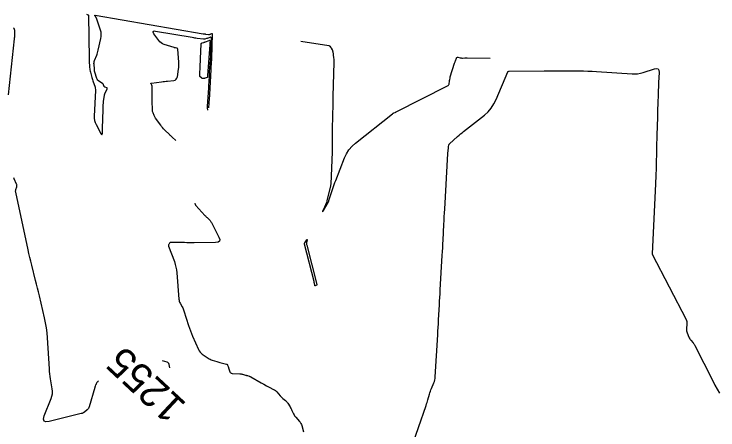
# Model space of a CAD drawing. Extents: x 658976 to 668721, y 639543 to 647196.
# Drawn here: x 660167.2 to 660311.5, y 642702 to 642787.3 of the extents above; entities that cross this region are included whole.
import ezdxf

# ---------------------------------------------------------------- set-up
doc = ezdxf.new("R2010")
doc.units = 0
for name, color, linetype in [('Ex_Contour Labels', 7, 'Continuous'), ('Ex_Major Contours', 7, 'Continuous'), ('Ex_Minor Contours', 7, 'Continuous')]:
    doc.layers.add(name, color=color, linetype=linetype)

msp = doc.modelspace()

# ---------------------------------------------------------------- linework, layer by layer
at = {"layer": 'Ex_Major Contours'}
for points in [[(660166.01, 642770.76), (660167.28, 642782.28), (660167.3, 642782.49), (660167.32, 642782.7), (660167.32, 642782.92), (660167.32, 642783.13), (660167.31, 642783.99), (660167.28, 642784.19), (660167.21, 642784.36), (660167.09, 642784.5)], [(660200.38, 642761.4), (660199.6, 642762.09), (660199.47, 642762.2), (660199.34, 642762.32), (660199.22, 642762.44), (660199.09, 642762.56), (660198.03, 642763.6), (660197.82, 642763.82), (660197.61, 642764.04), (660197.42, 642764.28), (660197.24, 642764.52), (660196.2, 642765.98), (660196.11, 642766.11), (660196.04, 642766.23), (660195.97, 642766.36), (660195.9, 642766.5), (660195.67, 642767.04), (660195.61, 642767.18), (660195.58, 642767.32), (660195.55, 642767.47), (660195.54, 642767.61), (660195.52, 642769.55), (660195.52, 642769.86), (660195.52, 642770.16), (660195.51, 642770.47), (660195.51, 642770.78), (660195.5, 642772.45), (660195.49, 642772.53), (660195.47, 642772.61), (660195.45, 642772.68), (660195.41, 642772.75), (660195.26, 642773.03), (660195.23, 642773.1), (660195.24, 642773.14), (660195.27, 642773.18), (660195.34, 642773.19), (660197.4, 642773.43), (660197.72, 642773.47), (660198.03, 642773.51), (660198.35, 642773.54), (660198.67, 642773.58), (660199.93, 642773.74), (660200.21, 642773.81), (660200.43, 642773.96), (660200.58, 642774.17), (660200.66, 642774.45), (660200.9, 642776), (660200.94, 642776.36), (660200.97, 642776.72), (660200.97, 642777.09), (660200.95, 642777.45), (660200.76, 642780.12), (660200.74, 642780.19), (660200.71, 642780.24), (660200.66, 642780.28), (660200.6, 642780.31), (660200.31, 642780.38), (660200.23, 642780.4), (660200.16, 642780.42), (660200.09, 642780.44), (660200.02, 642780.47), (660197.98, 642781.09), (660197.64, 642781.23), (660197.33, 642781.41), (660197.06, 642781.65), (660196.83, 642781.94), (660195.87, 642783.32), (660195.72, 642783.61), (660195.72, 642783.79), (660195.89, 642783.87), (660196.21, 642783.86), (660203.7, 642782.57), (660203.94, 642782.53), (660204.19, 642782.49), (660204.44, 642782.46), (660204.69, 642782.42), (660206.02, 642782.24), (660206.1, 642782.24), (660206.19, 642782.24), (660206.28, 642782.25), (660206.36, 642782.27), (660206.7, 642782.37), (660206.79, 642782.39), (660206.87, 642782.42), (660206.95, 642782.45), (660207.04, 642782.48), (660207.41, 642782.63), (660207.48, 642782.65), (660207.54, 642782.63), (660207.57, 642782.59), (660207.58, 642782.51), (660207.51, 642780.32), (660207.49, 642779.93), (660207.48, 642779.53), (660207.45, 642779.13), (660207.43, 642778.74), (660207.2, 642775.52), (660207.19, 642775.47), (660207.19, 642775.42), (660207.19, 642775.36), (660207.19, 642775.31), (660207.18, 642775.1), (660207.18, 642775.05), (660207.17, 642775), (660207.17, 642774.95), (660207.17, 642774.89), (660207.09, 642773.26), (660207.07, 642772.97), (660207.05, 642772.68), (660207.04, 642772.39), (660207.02, 642772.1), (660206.79, 642768.41), (660206.79, 642768.39), (660206.79, 642768.36), (660206.78, 642768.33), (660206.78, 642768.31), (660206.77, 642768.2), (660206.77, 642768.18), (660206.77, 642768.15), (660206.77, 642768.12), (660206.77, 642768.1), (660206.81, 642767.59)], [(660184.46, 642712.05), (660184.36, 642711.93), (660184.31, 642711.88), (660184.26, 642711.82), (660184.22, 642711.76), (660184.18, 642711.7), (660184.02, 642711.45), (660183.99, 642711.39), (660183.96, 642711.33), (660183.93, 642711.27), (660183.9, 642711.21), (660183.81, 642710.96), (660183.79, 642710.9), (660183.77, 642710.83), (660183.75, 642710.77), (660183.73, 642710.71), (660182.6, 642706.75), (660182.53, 642706.57), (660182.45, 642706.41), (660182.33, 642706.27), (660182.2, 642706.14), (660181.61, 642705.66), (660181.46, 642705.55), (660181.29, 642705.45), (660181.12, 642705.38), (660180.94, 642705.33), (660174.36, 642703.72), (660173.7, 642703.65), (660173.32, 642703.81), (660173.21, 642704.21), (660173.37, 642704.85), (660174.79, 642708.45), (660174.94, 642708.94), (660175.03, 642709.43), (660175.05, 642709.92), (660175, 642710.43), (660174.66, 642712.46), (660174.58, 642712.97), (660174.52, 642713.48), (660174.47, 642714), (660174.43, 642714.51), (660174.02, 642720.9), (660173.94, 642721.94), (660173.81, 642722.97), (660173.63, 642723.99), (660173.42, 642725.01), (660172.38, 642729.53), (660172.19, 642730.32), (660172, 642731.11), (660171.81, 642731.89), (660171.61, 642732.68), (660170.81, 642735.82), (660170.61, 642736.6), (660170.42, 642737.39), (660170.24, 642738.18), (660170.06, 642738.97), (660167.53, 642750.78), (660167.51, 642750.92), (660167.51, 642751.07), (660167.52, 642751.21), (660167.56, 642751.35), (660167.74, 642751.91), (660167.77, 642752.05), (660167.78, 642752.19), (660167.76, 642752.33), (660167.71, 642752.46), (660167.21, 642753.52), (660167.12, 642753.74)], [(660199.13, 642714.75), (660198.98, 642715.43), (660198.93, 642715.59), (660198.84, 642715.72), (660198.72, 642715.83), (660198.56, 642715.9), (660197.64, 642716.19), (660197.59, 642716.2)]]:
    msp.add_lwpolyline(points, dxfattribs=at)
at = {"layer": 'Ex_Minor Contours'}
for points in [[(660182.02, 642787.34), (660182.34, 642787.2), (660182.38, 642787.18), (660182.42, 642787.14), (660182.44, 642787.1), (660182.44, 642787.04), (660182.58, 642778.14), (660182.58, 642778.12), (660182.58, 642778.09), (660182.57, 642778.06), (660182.57, 642778.04), (660182.56, 642777.93), (660182.56, 642777.91), (660182.56, 642777.88), (660182.56, 642777.85), (660182.56, 642777.83), (660182.68, 642776.38), (660182.7, 642776.13), (660182.74, 642775.89), (660182.79, 642775.64), (660182.85, 642775.4), (660183.14, 642774.33), (660183.21, 642774.11), (660183.27, 642773.89), (660183.34, 642773.66), (660183.42, 642773.44), (660183.72, 642772.56), (660183.78, 642772.34), (660183.82, 642772.11), (660183.85, 642771.88), (660183.85, 642771.65), (660183.61, 642766.42), (660183.61, 642765.96), (660183.68, 642765.52), (660183.81, 642765.09), (660183.99, 642764.68), (660184.94, 642762.85), (660185.09, 642762.62), (660185.19, 642762.56), (660185.26, 642762.66), (660185.29, 642762.93), (660185.33, 642764.34), (660185.34, 642764.69), (660185.35, 642765.04), (660185.36, 642765.39), (660185.37, 642765.75), (660185.43, 642767.74), (660185.44, 642767.89), (660185.44, 642768.03), (660185.45, 642768.17), (660185.46, 642768.31), (660185.48, 642768.87), (660185.49, 642769.01), (660185.5, 642769.15), (660185.52, 642769.29), (660185.53, 642769.43), (660185.72, 642770.72), (660185.72, 642770.74), (660185.73, 642770.77), (660185.73, 642770.79), (660185.74, 642770.81), (660185.76, 642770.91), (660185.77, 642770.93), (660185.77, 642770.95), (660185.78, 642770.97), (660185.79, 642771), (660186.26, 642772.03), (660186.28, 642772.1), (660186.28, 642772.15), (660186.24, 642772.19), (660186.17, 642772.22), (660185.85, 642772.31), (660185.78, 642772.34), (660185.73, 642772.38), (660185.68, 642772.43), (660185.65, 642772.5), (660185.55, 642772.8), (660185.52, 642772.88), (660185.48, 642772.94), (660185.43, 642773), (660185.37, 642773.05), (660184.5, 642773.67), (660184.34, 642773.8), (660184.22, 642773.95), (660184.12, 642774.12), (660184.06, 642774.3), (660183.8, 642775.23), (660183.75, 642775.44), (660183.7, 642775.65), (660183.67, 642775.87), (660183.65, 642776.09), (660183.58, 642776.96), (660183.57, 642777.17), (660183.59, 642777.38), (660183.63, 642777.59), (660183.7, 642777.8), (660184.13, 642778.88), (660184.22, 642779.13), (660184.3, 642779.39), (660184.37, 642779.64), (660184.44, 642779.9), (660184.99, 642782.33), (660185.06, 642782.77), (660185.07, 642783.2), (660185.02, 642783.64), (660184.9, 642784.07), (660184.07, 642786.49), (660184.04, 642786.56), (660184.01, 642786.63), (660183.97, 642786.7), (660183.93, 642786.76), (660183.76, 642787.01), (660183.73, 642787.07), (660183.73, 642787.1), (660183.76, 642787.12), (660183.82, 642787.11), (660205.98, 642783.32), (660206.1, 642783.3), (660206.21, 642783.28), (660206.33, 642783.26), (660206.45, 642783.25), (660207.07, 642783.16), (660207.11, 642783.16), (660207.15, 642783.16), (660207.19, 642783.17), (660207.23, 642783.18), (660207.39, 642783.22), (660207.43, 642783.23), (660207.47, 642783.25), (660207.51, 642783.26), (660207.55, 642783.28), (660207.72, 642783.34), (660207.76, 642783.35), (660207.78, 642783.35), (660207.8, 642783.33), (660207.8, 642783.29), (660207.64, 642778.24), (660207.64, 642778.04), (660207.63, 642777.83), (660207.61, 642777.62), (660207.6, 642777.42), (660207.52, 642776.23), (660207.51, 642776.21), (660207.51, 642776.18), (660207.51, 642776.16), (660207.51, 642776.14), (660207.51, 642776.06), (660207.51, 642776.04), (660207.51, 642776.02), (660207.51, 642776), (660207.5, 642775.98), (660207.25, 642770.83), (660207.24, 642770.63), (660207.22, 642770.44), (660207.21, 642770.25), (660207.2, 642770.05), (660207.14, 642769.03), (660207.13, 642768.96), (660207.13, 642768.89), (660207.12, 642768.82), (660207.11, 642768.75), (660207.07, 642768.38), (660207.07, 642768.35), (660207.07, 642768.32), (660207.07, 642768.29), (660207.07, 642768.27), (660207.08, 642768.09)], [(660225.98, 642781.76), (660231.69, 642780.88), (660231.75, 642780.87), (660231.8, 642780.84), (660231.85, 642780.81), (660231.9, 642780.76), (660232.06, 642780.57), (660232.1, 642780.51), (660232.14, 642780.46), (660232.18, 642780.41), (660232.21, 642780.35), (660232.4, 642779.99), (660232.44, 642779.91), (660232.47, 642779.83), (660232.5, 642779.74), (660232.52, 642779.65), (660232.7, 642778.36), (660232.73, 642778.12), (660232.75, 642777.87), (660232.76, 642777.62), (660232.76, 642777.38), (660232.57, 642770.52), (660232.55, 642769.7), (660232.53, 642768.88), (660232.51, 642768.06), (660232.5, 642767.24), (660232.43, 642763), (660232.42, 642762.66), (660232.42, 642762.33), (660232.42, 642762), (660232.42, 642761.66), (660232.42, 642760.33), (660232.42, 642760), (660232.42, 642759.67), (660232.41, 642759.33), (660232.4, 642759), (660232.13, 642752.53), (660232.12, 642752.49), (660232.12, 642752.45), (660232.12, 642752.41), (660232.11, 642752.37), (660232.09, 642752.22), (660232.08, 642752.18), (660232.08, 642752.14), (660232.07, 642752.11), (660232.06, 642752.07), (660231.34, 642748.99), (660231.34, 642748.97), (660231.34, 642748.96), (660231.33, 642748.95), (660231.33, 642748.94), (660231.3, 642748.87), (660231.29, 642748.84), (660231.28, 642748.83), (660230.53, 642747.09), (660230.44, 642746.86), (660230.43, 642746.78), (660230.48, 642746.84), (660230.61, 642747.05), (660231.59, 642748.69), (660231.61, 642748.72), (660231.62, 642748.75), (660231.64, 642748.79), (660231.65, 642748.82), (660231.69, 642748.97), (660231.7, 642749), (660231.71, 642749.04), (660231.72, 642749.07), (660231.73, 642749.11), (660232.53, 642751.51), (660232.67, 642751.92), (660232.82, 642752.33), (660232.97, 642752.74), (660233.12, 642753.15), (660234.94, 642757.81), (660235.34, 642758.69), (660235.85, 642759.48), (660236.47, 642760.2), (660237.18, 642760.85), (660244.8, 642766.85), (660244.82, 642766.87), (660244.84, 642766.88), (660244.86, 642766.9), (660244.87, 642766.92), (660244.95, 642767.03), (660244.96, 642767.04), (660244.97, 642767.04), (660244.98, 642767.05), (660244.98, 642767.05), (660245.02, 642767.05), (660245.03, 642767.05), (660245.04, 642767.05), (660245.05, 642767.05), (660245.06, 642767.05), (660245.31, 642767.16), (660245.36, 642767.18), (660245.4, 642767.2), (660245.45, 642767.23), (660245.49, 642767.25), (660256.08, 642772.59), (660256.19, 642772.66), (660256.27, 642772.75), (660256.33, 642772.86), (660256.36, 642772.98), (660256.47, 642773.67), (660256.48, 642773.74), (660256.49, 642773.8), (660256.5, 642773.87), (660256.51, 642773.93), (660256.56, 642774.19), (660256.57, 642774.26), (660256.58, 642774.32), (660256.6, 642774.39), (660256.62, 642774.45), (660257.5, 642777.26), (660257.54, 642777.38), (660257.59, 642777.51), (660257.63, 642777.64), (660257.67, 642777.76), (660257.86, 642778.29), (660257.91, 642778.39), (660257.98, 642778.45), (660258.07, 642778.47), (660258.17, 642778.47), (660258.63, 642778.37), (660258.74, 642778.35), (660258.86, 642778.33), (660258.97, 642778.32), (660259.09, 642778.32), (660259.58, 642778.33), (660259.7, 642778.33), (660259.82, 642778.33), (660259.94, 642778.33), (660260.06, 642778.33), (660264.82, 642778.3)], [(660248.51, 642697.99), (660251.67, 642707.03), (660251.77, 642707.32), (660251.86, 642707.6), (660251.95, 642707.89), (660252.03, 642708.18), (660252.35, 642709.34), (660252.43, 642709.63), (660252.53, 642709.91), (660252.63, 642710.2), (660252.74, 642710.47), (660253.24, 642711.65), (660253.35, 642711.95), (660253.43, 642712.24), (660253.49, 642712.55), (660253.52, 642712.86), (660254.04, 642721.49), (660254.08, 642722.25), (660254.13, 642723.02), (660254.17, 642723.79), (660254.21, 642724.56), (660254.38, 642727.64), (660254.43, 642728.4), (660254.47, 642729.17), (660254.52, 642729.94), (660254.56, 642730.71), (660254.97, 642737.79), (660255.02, 642738.59), (660255.06, 642739.38), (660255.1, 642740.18), (660255.15, 642740.97), (660255.31, 642744.15), (660255.35, 642744.95), (660255.39, 642745.74), (660255.43, 642746.54), (660255.48, 642747.33), (660256.12, 642758.74), (660256.13, 642758.87), (660256.14, 642758.99), (660256.15, 642759.12), (660256.16, 642759.25), (660256.22, 642759.87), (660256.23, 642759.94), (660256.24, 642760.01), (660256.25, 642760.09), (660256.27, 642760.16), (660256.33, 642760.46), (660256.35, 642760.53), (660256.38, 642760.6), (660256.42, 642760.66), (660256.47, 642760.71), (660258.12, 642762.21), (660258.42, 642762.47), (660258.72, 642762.73), (660259.02, 642762.98), (660259.33, 642763.23), (660263.61, 642766.62), (660264.37, 642767.3), (660265.03, 642768.06), (660265.58, 642768.9), (660266.02, 642769.81), (660268.39, 642775.52), (660268.4, 642775.52), (660268.4, 642775.53), (660268.41, 642775.54), (660268.41, 642775.54), (660268.43, 642775.57), (660268.44, 642775.57), (660268.44, 642775.58), (660268.45, 642775.58), (660268.46, 642775.58), (660268.59, 642775.61), (660268.62, 642775.61), (660268.65, 642775.61), (660268.67, 642775.61), (660268.7, 642775.62), (660275.88, 642775.69), (660276.77, 642775.7), (660277.67, 642775.7), (660278.56, 642775.7), (660279.46, 642775.7), (660283.03, 642775.68), (660283.93, 642775.67), (660284.82, 642775.64), (660285.71, 642775.61), (660286.6, 642775.55), (660293.88, 642775.08), (660294.45, 642775.07), (660295.02, 642775.11), (660295.59, 642775.21), (660296.15, 642775.36), (660298.49, 642776.1), (660298.92, 642776.18), (660299.22, 642776.08), (660299.39, 642775.82), (660299.43, 642775.38), (660299.32, 642773.31), (660299.3, 642772.79), (660299.28, 642772.28), (660299.25, 642771.76), (660299.24, 642771.24), (660299.14, 642768.62), (660299.12, 642768.01), (660299.1, 642767.4), (660299.08, 642766.79), (660299.07, 642766.18), (660298.97, 642762.51), (660298.95, 642761.69), (660298.93, 642760.87), (660298.91, 642760.06), (660298.89, 642759.24), (660298.73, 642753.53), (660298.73, 642753.45), (660298.73, 642753.36), (660298.72, 642753.27), (660298.72, 642753.18), (660298.7, 642752.83), (660298.7, 642752.74), (660298.69, 642752.65), (660298.69, 642752.56), (660298.69, 642752.47), (660298.01, 642738.16), (660298.01, 642738.16), (660298, 642738.15), (660298, 642738.14), (660298, 642738.11), (660298, 642738.1), (660298, 642738.09), (660298, 642738.06), (660298, 642738.05), (660298, 642738.04), (660298.01, 642738.04), (660298.01, 642738.03), (660304.96, 642724.65), (660305.06, 642724.43), (660305.12, 642724.21), (660305.15, 642723.98), (660305.14, 642723.74), (660305.04, 642722.73), (660305.04, 642722.51), (660305.05, 642722.3), (660305.1, 642722.1), (660305.17, 642721.9), (660305.55, 642721.03), (660305.62, 642720.87), (660305.71, 642720.71), (660305.81, 642720.57), (660305.92, 642720.43), (660306.39, 642719.89), (660306.51, 642719.75), (660306.61, 642719.6), (660306.7, 642719.45), (660306.79, 642719.29), (660310.44, 642712.04), (660310.87, 642711.2), (660311.32, 642710.37), (660311.8, 642709.56)], [(660204.23, 642748.5), (660204.32, 642748.28), (660204.33, 642748.25), (660204.33, 642748.23), (660204.35, 642748.21), (660204.36, 642748.19), (660204.4, 642748.11), (660204.41, 642748.09), (660204.43, 642748.07), (660204.44, 642748.05), (660204.46, 642748.04), (660206.3, 642746.03), (660206.41, 642745.91), (660206.52, 642745.79), (660206.64, 642745.67), (660206.76, 642745.56), (660207.24, 642745.1), (660207.36, 642744.99), (660207.46, 642744.86), (660207.55, 642744.73), (660207.63, 642744.58), (660209.17, 642741.57), (660209.34, 642741.09), (660209.28, 642740.75), (660209, 642740.54), (660208.5, 642740.46), (660204.13, 642740.42), (660203.63, 642740.42), (660203.13, 642740.42), (660202.63, 642740.42), (660202.14, 642740.43), (660199.31, 642740.48), (660199.23, 642740.48), (660199.16, 642740.45), (660199.11, 642740.4), (660199.06, 642740.34), (660198.89, 642740.03), (660198.86, 642739.96), (660198.85, 642739.88), (660198.85, 642739.8), (660198.87, 642739.72), (660200.05, 642736.54), (660200.24, 642735.97), (660200.38, 642735.4), (660200.49, 642734.82), (660200.56, 642734.23), (660200.98, 642728.82), (660201.01, 642728.6), (660201.06, 642728.39), (660201.13, 642728.19), (660201.23, 642727.99), (660201.67, 642727.22), (660201.78, 642727.02), (660201.87, 642726.82), (660201.95, 642726.61), (660202.02, 642726.4), (660202.95, 642723.44), (660203.14, 642722.88), (660203.34, 642722.33), (660203.55, 642721.78), (660203.78, 642721.23), (660204.98, 642718.49), (660205.13, 642718.21), (660205.31, 642717.96), (660205.52, 642717.74), (660205.77, 642717.54), (660206.97, 642716.72), (660207.17, 642716.6), (660207.38, 642716.49), (660207.59, 642716.39), (660207.82, 642716.31), (660208.75, 642716), (660208.96, 642715.94), (660209.18, 642715.88), (660209.39, 642715.82), (660209.61, 642715.76), (660210.77, 642715.5), (660210.84, 642715.47), (660210.9, 642715.43), (660210.94, 642715.38), (660210.97, 642715.31), (660211.08, 642715.02), (660211.11, 642714.94), (660211.13, 642714.87), (660211.16, 642714.8), (660211.18, 642714.72), (660211.44, 642713.93), (660211.51, 642713.79), (660211.6, 642713.69), (660211.72, 642713.63), (660211.87, 642713.6), (660213.44, 642713.51), (660213.58, 642713.5), (660213.72, 642713.48), (660213.87, 642713.45), (660214.01, 642713.42), (660214.66, 642713.24), (660214.75, 642713.22), (660214.84, 642713.19), (660214.93, 642713.17), (660215.02, 642713.14), (660215.37, 642713.02), (660215.46, 642712.99), (660215.54, 642712.96), (660215.62, 642712.92), (660215.71, 642712.87), (660217.82, 642711.66), (660217.95, 642711.58), (660218.09, 642711.5), (660218.23, 642711.43), (660218.37, 642711.35), (660218.92, 642711.05), (660219.06, 642710.98), (660219.2, 642710.91), (660219.34, 642710.84), (660219.48, 642710.77), (660220.38, 642710.32), (660220.57, 642710.21), (660220.75, 642710.09), (660220.91, 642709.95), (660221.06, 642709.79), (660221.75, 642708.96), (660221.87, 642708.82), (660222, 642708.69), (660222.13, 642708.57), (660222.26, 642708.45), (660222.83, 642708), (660222.96, 642707.88), (660223.09, 642707.75), (660223.2, 642707.61), (660223.3, 642707.46), (660223.76, 642706.7), (660223.87, 642706.53), (660223.97, 642706.35), (660224.06, 642706.17), (660224.15, 642705.99), (660224.49, 642705.26), (660224.59, 642705.08), (660224.69, 642704.91), (660224.81, 642704.75), (660224.94, 642704.59), (660225.7, 642703.75), (660225.85, 642703.55), (660225.99, 642703.34), (660226.09, 642703.12), (660226.17, 642702.88), (660226.51, 642701.63)]]:
    msp.add_lwpolyline(points, dxfattribs=at)
for points in [[(660207.26, 642781.97), (660207.31, 642781.95), (660207.35, 642781.9), (660207.36, 642781.82), (660207.34, 642781.43), (660207.34, 642781.33), (660207.34, 642781.23), (660207.33, 642781.13), (660207.32, 642781.03), (660206.87, 642774.73), (660206.87, 642774.69), (660206.87, 642774.65), (660206.87, 642774.61), (660206.86, 642774.57), (660206.86, 642774.41), (660206.85, 642774.37), (660206.84, 642774.35), (660206.81, 642774.32), (660206.78, 642774.31), (660206.38, 642774.18), (660206.31, 642774.16), (660206.25, 642774.15), (660206.18, 642774.14), (660206.11, 642774.14), (660205.83, 642774.13), (660205.77, 642774.14), (660205.7, 642774.16), (660205.65, 642774.19), (660205.59, 642774.23), (660205.35, 642774.45), (660205.29, 642774.5), (660205.26, 642774.57), (660205.24, 642774.63), (660205.24, 642774.71), (660205.35, 642776.76), (660205.37, 642777.13), (660205.39, 642777.5), (660205.41, 642777.86), (660205.42, 642778.23), (660205.55, 642781.19), (660205.57, 642781.28), (660205.6, 642781.35), (660205.66, 642781.4), (660205.74, 642781.43), (660206.1, 642781.53), (660206.18, 642781.56), (660206.27, 642781.59), (660206.36, 642781.62), (660206.45, 642781.65), (660207.18, 642781.95)], [(660226.71, 642740.16), (660226.71, 642740.19), (660226.72, 642740.21), (660226.72, 642740.23), (660226.75, 642740.33), (660226.76, 642740.35), (660226.77, 642740.37), (660226.78, 642740.4), (660226.8, 642740.42), (660227.18, 642740.98), (660227.24, 642741.06), (660227.27, 642741.08), (660227.28, 642741.04), (660227.27, 642740.95), (660227.16, 642740.43), (660227.14, 642740.3), (660227.14, 642740.17), (660227.15, 642740.05), (660227.18, 642739.92), (660229.24, 642731.82), (660229.25, 642731.8), (660229.24, 642731.78), (660229.24, 642731.76), (660229.23, 642731.74), (660229.18, 642731.64), (660229.17, 642731.64), (660229.17, 642731.63), (660229.16, 642731.63), (660229.15, 642731.63), (660229.11, 642731.63), (660229.11, 642731.63), (660229.1, 642731.63), (660229.09, 642731.63), (660229.08, 642731.63), (660228.92, 642731.57), (660228.9, 642731.57), (660228.87, 642731.57), (660228.86, 642731.59), (660228.85, 642731.61), (660228.76, 642732.09), (660228.74, 642732.18), (660228.72, 642732.27), (660228.7, 642732.36), (660228.68, 642732.45), (660226.72, 642740.14)]]:
    msp.add_lwpolyline(points, close=True, dxfattribs=at)

# ---------------------------------------------------------------- texts
at = {"layer": 'Ex_Contour Labels'}
msp.add_text('1255', height=6, rotation=136.9037, dxfattribs=at).set_placement((660202.74, 642707.28))

doc.saveas('drawing.dxf')
